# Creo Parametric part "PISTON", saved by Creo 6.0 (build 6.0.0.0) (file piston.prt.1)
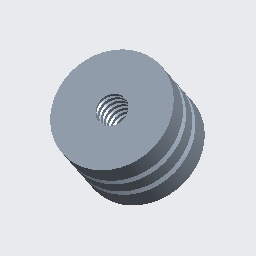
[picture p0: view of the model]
Units: millimeter Newton Second (mmNs); MM, TONNE, SECS

Created from: MMNS_PART_SOLID.PRT

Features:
  1. datum plane "RIGHT"
  2. datum plane "TOP"
  3. datum plane "FRONT"
  4. coordinate system
  5. sketch "Sketch 1"
  6. protrusion "Blend 1"
  7. sketch "Sketch 2"
  8. extruded cut "Extrude 1"
  9. sketch "Sketch 3"
  10. sketch "Sketch 4", "A_2"
  11. cut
